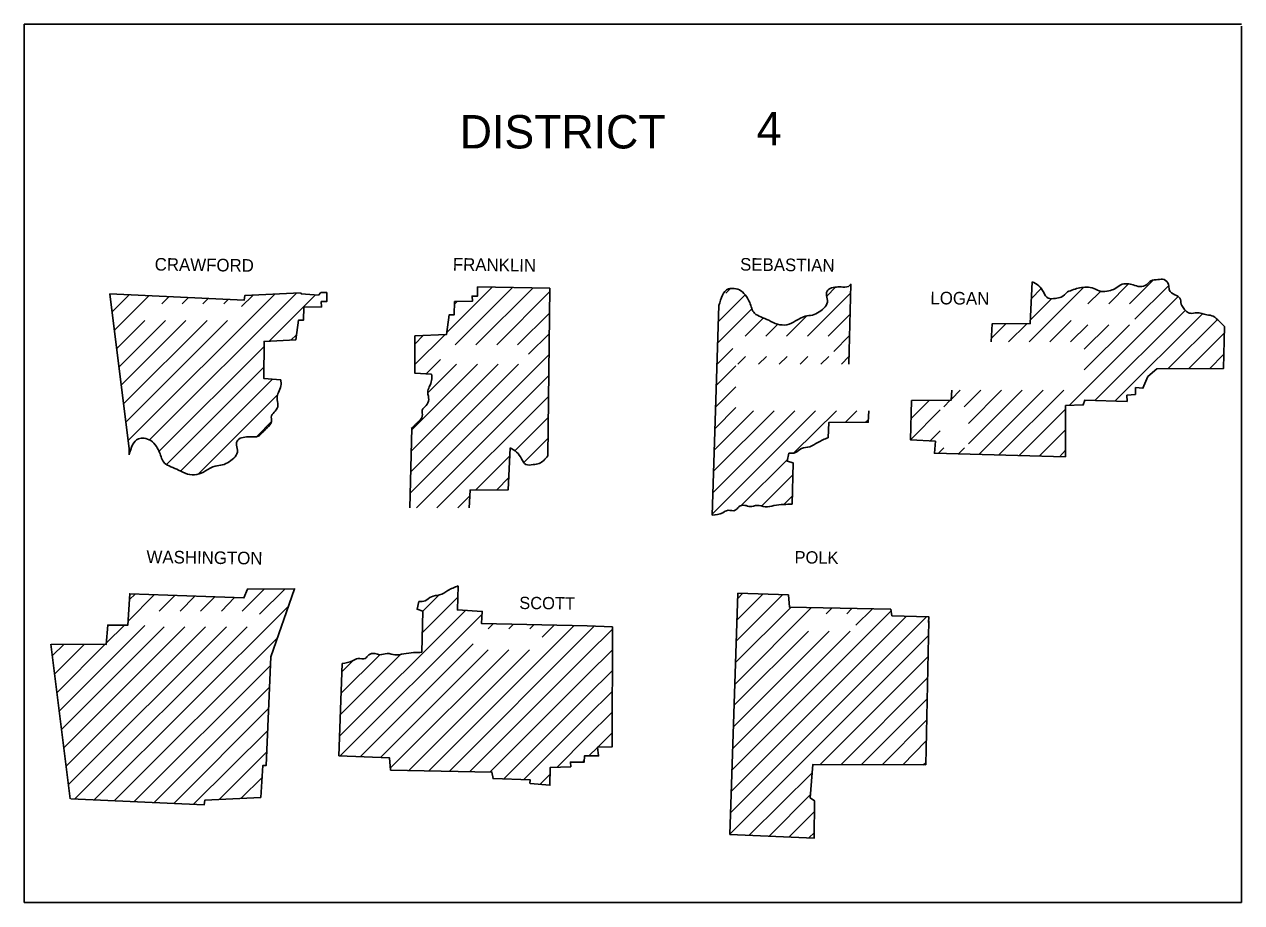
# Model space of a CAD drawing. Extents: x 76 to 6945, y -3933 to 2152.
# Drawn here: x 6125.3 to 6541, y -2439.5 to -2139.5 of the extents above; entities that cross this region are included whole.
import ezdxf

# ---------------------------------------------------------------- set-up
doc = ezdxf.new("R2010")
doc.units = 0
doc.layers.add('R_Draft', color=7, linetype='Continuous')

msp = doc.modelspace()

# ---------------------------------------------------------------- linework, layer by layer
at = {"layer": 'R_Draft'}
msp.add_line((6541.01, -2140.12), (6541.01, -2439.52), dxfattribs=at)
for points in [[(6125.31, -2439.52), (6125.31, -2139.52), (6541.01, -2139.52)], [(6455.51, -2248.02), (6455.81, -2241.82), (6468.81, -2241.72), (6469.51, -2227.42)], [(6502.71, -2235.02), (6510.71, -2227.02)], [(6154.51, -2231.62), (6200.41, -2233.72), (6200.61, -2232.12), (6219.61, -2231.22)], [(6161.11, -2286.52), (6161.11, -2284.52), (6154.51, -2231.62)], [(6155.31, -2237.72), (6161.11, -2231.92)], [(6156.11, -2244.02), (6167.81, -2232.22)], [(6160.81, -2281.62), (6210.81, -2231.72)], [(6168.11, -2281.42), (6218.31, -2231.32)], [(6199.51, -2235.92), (6203.31, -2232.12)], [(6228.61, -2231.12), (6228.61, -2234.22), (6226.71, -2234.22), (6226.81, -2236.02), (6220.71, -2236.12), (6220.61, -2240.62), (6218.91, -2240.62), (6218.01, -2247.32), (6207.21, -2247.82), (6207.11, -2260.52), (6212.91, -2260.92)], [(6208.91, -2247.72), (6224.71, -2231.92)], [(6219.81, -2231.22), (6219.81, -2231.52), (6225.71, -2232.02), (6226.61, -2231.12), (6228.61, -2231.12)], [(6264.41, -2259.02), (6258.61, -2258.62), (6258.71, -2245.92), (6269.51, -2245.42), (6270.41, -2238.72), (6272.11, -2238.72), (6272.21, -2234.22), (6278.31, -2234.12), (6278.21, -2232.32), (6280.11, -2232.32), (6280.11, -2229.22)], [(6269.61, -2244.82), (6285.01, -2229.42)], [(6272.41, -2249.02), (6292.01, -2229.42)], [(6279.51, -2249.02), (6298.91, -2229.62)], [(6280.11, -2229.22), (6304.81, -2229.62)], [(6286.61, -2249.02), (6304.71, -2230.82)], [(6304.81, -2229.62), (6304.11, -2286.92)], [(6362.21, -2241.12), (6371.41, -2232.02)], [(6364.91, -2231.32), (6366.61, -2229.62)], [(6392.71, -2246.02), (6407.51, -2231.22)], [(6399.31, -2232.32), (6402.31, -2229.32)], [(6407.61, -2228.22), (6406.91, -2255.62)], [(6468.41, -2248.02), (6487.01, -2229.42)], [(6469.21, -2233.12), (6472.41, -2229.92)], [(6488.51, -2235.02), (6492.81, -2230.72)], [(6495.61, -2235.02), (6502.31, -2228.32)], [(6504.51, -2240.22), (6516.01, -2228.82)], [(6172.21, -2235.02), (6174.61, -2232.62)], [(6179.21, -2235.02), (6181.31, -2232.92)], [(6186.21, -2235.02), (6188.11, -2233.12)], [(6193.41, -2235.02), (6194.91, -2233.52)], [(6272.11, -2235.22), (6273.11, -2234.22)], [(6360.21, -2307.22), (6362.51, -2235.52)], [(6468.81, -2240.62), (6476.01, -2233.42)], [(6482.21, -2269.62), (6519.21, -2232.62)], [(6293.71, -2249.02), (6304.71, -2238.02)], [(6362.11, -2248.32), (6373.81, -2236.62)], [(6371.51, -2246.02), (6377.61, -2239.92)], [(6385.61, -2246.02), (6392.61, -2239.02)], [(6399.81, -2246.02), (6407.31, -2238.52)], [(6490.91, -2268.02), (6521.71, -2237.22)], [(6497.71, -2268.22), (6527.61, -2238.42)], [(6515.81, -2257.22), (6532.71, -2240.32)], [(6156.91, -2250.22), (6166.51, -2240.72)], [(6157.71, -2256.52), (6173.51, -2240.72)], [(6158.41, -2262.82), (6180.51, -2240.72)], [(6159.21, -2269.12), (6187.71, -2240.72)], [(6160.01, -2275.42), (6194.71, -2240.72)], [(6378.51, -2246.02), (6382.51, -2242.02)], [(6455.61, -2246.72), (6460.51, -2241.82)], [(6461.41, -2248.02), (6467.61, -2241.82)], [(6475.51, -2248.02), (6482.81, -2240.72)], [(6535.21, -2242.72), (6534.81, -2257.12), (6512.01, -2257.22), (6509.01, -2259.82), (6507.31, -2263.82), (6504.81, -2263.62), (6504.71, -2265.92), (6501.81, -2266.22), (6501.91, -2268.32), (6487.41, -2267.92), (6486.91, -2269.52), (6480.91, -2269.72), (6480.81, -2287.22)], [(6482.61, -2248.02), (6488.51, -2242.12)], [(6487.21, -2257.52), (6502.71, -2242.12)], [(6487.21, -2250.52), (6495.61, -2242.12)], [(6216.31, -2247.42), (6218.21, -2245.52)], [(6258.61, -2255.72), (6268.91, -2245.52)], [(6258.61, -2248.72), (6261.51, -2245.82)], [(6297.51, -2252.22), (6304.61, -2245.12)], [(6401.71, -2251.22), (6407.11, -2245.82)], [(6522.91, -2257.22), (6535.11, -2244.92)], [(6171.41, -2285.32), (6207.21, -2249.52)], [(6257.01, -2299.82), (6304.51, -2252.32)], [(6361.91, -2255.62), (6367.31, -2250.22)], [(6368.91, -2255.62), (6371.61, -2252.92)], [(6376.01, -2255.62), (6378.71, -2252.92)], [(6383.11, -2255.62), (6385.81, -2252.92)], [(6390.21, -2255.62), (6392.91, -2252.92)], [(6397.31, -2255.62), (6400.01, -2252.92)], [(6404.31, -2255.62), (6406.91, -2253.02)], [(6530.01, -2257.22), (6534.91, -2252.22)], [(6173.91, -2289.82), (6207.21, -2256.52)], [(6257.21, -2292.52), (6294.11, -2255.62)], [(6257.41, -2285.32), (6287.11, -2255.62)], [(6257.61, -2278.02), (6280.01, -2255.62)], [(6262.61, -2258.82), (6267.41, -2254.02)], [(6263.21, -2265.32), (6272.91, -2255.62)], [(6361.61, -2262.92), (6368.31, -2256.22)], [(6178.71, -2292.02), (6210.11, -2260.72)], [(6259.21, -2304.72), (6304.41, -2259.52)], [(6361.41, -2270.22), (6368.31, -2263.32)], [(6480.81, -2287.22), (6436.11, -2286.02), (6436.41, -2281.92), (6427.91, -2281.42), (6428.31, -2268.02), (6441.81, -2267.92), (6442.01, -2264.52)], [(6441.91, -2267.52), (6444.91, -2264.52)], [(6446.31, -2270.12), (6451.91, -2264.52)], [(6447.71, -2282.82), (6466.11, -2264.52)], [(6447.71, -2275.82), (6459.01, -2264.52)], [(6451.31, -2286.42), (6473.21, -2264.52)], [(6458.11, -2286.62), (6480.31, -2264.52)], [(6184.71, -2293.12), (6211.81, -2266.12)], [(6266.21, -2304.72), (6304.31, -2266.62)], [(6428.21, -2274.12), (6434.41, -2267.92)], [(6439.31, -2270.12), (6441.51, -2267.92)], [(6293.01, -2285.02), (6304.21, -2273.82)], [(6360.31, -2306.72), (6395.51, -2271.52)], [(6360.51, -2299.42), (6388.41, -2271.52)], [(6360.71, -2292.12), (6381.41, -2271.52)], [(6360.91, -2284.92), (6374.31, -2271.52)], [(6361.21, -2277.52), (6368.31, -2270.42)], [(6388.11, -2285.92), (6402.61, -2271.52)], [(6413.71, -2271.52), (6413.51, -2275.42), (6400.01, -2275.52), (6399.81, -2280.72)], [(6405.71, -2275.42), (6409.61, -2271.52)], [(6427.91, -2281.42), (6438.11, -2271.22)], [(6465.11, -2286.72), (6481.01, -2270.82)], [(6204.81, -2280.22), (6209.71, -2275.22)], [(6256.91, -2304.72), (6257.61, -2277.42)], [(6412.71, -2275.42), (6413.51, -2274.72)], [(6471.91, -2287.02), (6481.01, -2277.92)], [(6296.01, -2289.02), (6304.21, -2280.92)], [(6434.71, -2281.72), (6438.11, -2278.32)], [(6291.21, -2284.22), (6290.51, -2298.52), (6277.51, -2298.62), (6277.21, -2304.72)], [(6386.41, -2286.02), (6385.81, -2288.72), (6387.81, -2289.32), (6387.51, -2303.42)], [(6437.51, -2286.02), (6439.31, -2284.22)], [(6444.31, -2286.22), (6446.41, -2284.22)], [(6478.81, -2287.22), (6480.91, -2285.02)], [(6279.41, -2298.62), (6291.21, -2286.82)], [(6370.11, -2303.92), (6385.91, -2288.12)], [(6286.61, -2298.52), (6290.71, -2294.32)], [(6377.11, -2304.02), (6387.81, -2293.32)], [(6273.31, -2304.72), (6277.41, -2300.62)], [(6384.81, -2303.42), (6387.61, -2300.62)], [(6273.41, -2331.32), (6273.21, -2339.52), (6281.71, -2340.02), (6281.41, -2344.12), (6317.51, -2345.02)], [(6134.61, -2351.22), (6153.31, -2351.32), (6153.81, -2344.72), (6160.71, -2344.72), (6161.31, -2334.02), (6200.31, -2335.42), (6201.51, -2332.42), (6217.61, -2332.32), (6209.51, -2355.52), (6207.91, -2392.62), (6206.71, -2392.72), (6206.11, -2403.62)], [(6160.81, -2343.42), (6169.81, -2334.32)], [(6161.21, -2336.02), (6163.11, -2334.12)], [(6171.41, -2339.92), (6176.71, -2334.62)], [(6178.51, -2339.92), (6183.51, -2334.82)], [(6185.51, -2339.92), (6190.41, -2335.02)], [(6192.61, -2339.92), (6197.11, -2335.32)], [(6199.71, -2339.92), (6207.21, -2332.42)], [(6205.61, -2341.02), (6214.31, -2332.42)], [(6261.31, -2340.12), (6266.91, -2334.52)], [(6261.31, -2347.22), (6273.31, -2335.22)], [(6366.21, -2416.22), (6369.01, -2333.82)], [(6368.51, -2350.12), (6384.21, -2334.42)], [(6368.71, -2342.92), (6377.41, -2334.22)], [(6368.91, -2333.82), (6386.21, -2334.42), (6386.61, -2338.62), (6421.21, -2339.32), (6421.61, -2341.52), (6434.21, -2341.92), (6434.11, -2343.82)], [(6368.91, -2335.62), (6370.61, -2333.92)], [(6149.31, -2404.32), (6215.51, -2338.22)], [(6232.91, -2382.62), (6275.91, -2339.72)], [(6261.11, -2354.02), (6261.41, -2339.92), (6259.41, -2339.32), (6260.01, -2336.62)], [(6367.01, -2394.12), (6421.31, -2339.82)], [(6368.01, -2364.92), (6394.01, -2338.82)], [(6368.21, -2357.52), (6387.01, -2338.72)], [(6399.11, -2340.82), (6400.91, -2339.02)], [(6406.21, -2340.82), (6407.81, -2339.12)], [(6409.31, -2344.72), (6414.81, -2339.32)], [(6233.21, -2389.42), (6281.51, -2341.12)], [(6283.71, -2346.02), (6285.51, -2344.22)], [(6290.81, -2346.02), (6292.31, -2344.42)], [(6434.21, -2343.22), (6433.11, -2392.42), (6394.61, -2392.32), (6393.71, -2403.72), (6395.11, -2404.72), (6395.01, -2417.52), (6366.21, -2416.22)], [(6366.51, -2408.82), (6433.41, -2341.92)], [(6366.81, -2401.42), (6426.51, -2341.72)], [(6137.21, -2374.12), (6166.51, -2344.82)], [(6138.01, -2380.42), (6173.11, -2345.32)], [(6138.81, -2386.62), (6180.11, -2345.32)], [(6139.61, -2392.92), (6187.21, -2345.32)], [(6140.41, -2399.22), (6194.31, -2345.32)], [(6142.61, -2404.02), (6201.41, -2345.32)], [(6153.41, -2350.82), (6159.51, -2344.72)], [(6263.61, -2394.42), (6313.01, -2345.02)], [(6270.51, -2394.62), (6317.51, -2347.52)], [(6297.91, -2346.02), (6299.31, -2344.62)], [(6302.11, -2348.82), (6306.11, -2344.82)], [(6317.51, -2345.02), (6326.11, -2345.32)], [(6317.51, -2347.52), (6319.91, -2345.12)], [(6326.11, -2345.32), (6326.01, -2386.32), (6321.01, -2386.42), (6321.41, -2389.42), (6317.51, -2389.32)], [(6317.51, -2354.62), (6326.11, -2346.12)], [(6366.31, -2416.02), (6434.11, -2348.22)], [(6367.21, -2386.82), (6407.31, -2346.82)], [(6367.51, -2379.52), (6400.21, -2346.82)], [(6367.71, -2372.12), (6393.11, -2346.82)], [(6140.91, -2404.02), (6134.31, -2351.22)], [(6134.81, -2355.22), (6138.91, -2351.22)], [(6135.61, -2361.52), (6145.91, -2351.22)], [(6136.41, -2367.82), (6152.91, -2351.22)], [(6156.11, -2404.62), (6211.71, -2349.02)], [(6240.11, -2389.62), (6278.61, -2351.12)], [(6233.21, -2375.32), (6253.91, -2354.62)], [(6233.51, -2367.92), (6246.71, -2354.82)], [(6246.91, -2389.92), (6283.71, -2353.12)], [(6250.41, -2393.42), (6290.81, -2353.12)], [(6256.71, -2394.22), (6297.81, -2353.12)], [(6277.41, -2394.72), (6317.51, -2354.62)], [(6317.51, -2361.72), (6326.11, -2353.12)], [(6397.11, -2392.32), (6433.91, -2355.42)], [(6162.81, -2405.02), (6209.41, -2358.52)], [(6232.71, -2389.42), (6233.81, -2357.82)], [(6233.81, -2360.62), (6237.41, -2357.02)], [(6317.51, -2368.82), (6326.11, -2360.22)], [(6284.31, -2394.92), (6317.51, -2361.72)], [(6404.21, -2392.32), (6433.71, -2362.72)], [(6169.61, -2405.32), (6209.01, -2365.92)], [(6289.21, -2397.12), (6317.51, -2368.82)], [(6317.51, -2375.82), (6326.01, -2367.42)], [(6176.41, -2405.62), (6208.71, -2373.22)], [(6411.21, -2392.32), (6433.61, -2369.92)], [(6295.91, -2397.42), (6317.51, -2375.82)], [(6317.51, -2382.92), (6326.01, -2374.42)], [(6418.21, -2392.42), (6433.41, -2377.22)], [(6183.11, -2405.92), (6208.41, -2380.72)], [(6321.11, -2386.42), (6326.01, -2381.52)], [(6307.31, -2393.22), (6317.51, -2382.92)], [(6425.31, -2392.42), (6433.21, -2384.42)], [(6191.81, -2404.32), (6208.01, -2388.12)], [(6297.91, -2398.82), (6298.01, -2397.52), (6285.41, -2397.12), (6285.01, -2394.92), (6250.41, -2394.22), (6250.01, -2390.02), (6232.71, -2389.42)], [(6317.51, -2389.32), (6316.61, -2389.32), (6316.51, -2391.52), (6311.81, -2391.52), (6311.91, -2393.12), (6304.91, -2393.32), (6304.81, -2399.42), (6298.01, -2398.82)], [(6318.11, -2389.32), (6321.01, -2386.52)], [(6316.01, -2391.52), (6316.51, -2391.02)], [(6432.41, -2392.42), (6433.11, -2391.72)], [(6199.31, -2403.82), (6206.51, -2396.72)], [(6301.41, -2399.02), (6304.91, -2395.62)], [(6372.81, -2416.52), (6394.41, -2395.02)], [(6379.61, -2416.82), (6393.81, -2402.62)], [(6206.11, -2403.62), (6186.91, -2404.52), (6186.71, -2406.12), (6141.21, -2404.02)], [(6386.41, -2417.12), (6395.11, -2408.42)], [(6393.21, -2417.42), (6395.11, -2415.52)], [(6541.01, -2439.52), (6125.31, -2439.52)]]:
    msp.add_lwpolyline(points, dxfattribs=at)
for points in [[(6362.51, -2235.52), (6365.81, -2229.92), (6367.71, -2229.72), (6370.01, -2230.52), (6371.91, -2232.52), (6373.01, -2234.52), (6374.71, -2238.22), (6376.81, -2239.42), (6379.51, -2240.62), (6382.51, -2241.92), (6385.71, -2242.12), (6388.71, -2240.82), (6392.01, -2239.22), (6394.41, -2238.82), (6396.71, -2237.72), (6398.81, -2236.02), (6399.61, -2233.82), (6399.21, -2231.52), (6400.01, -2230.02), (6402.11, -2229.32), (6404.21, -2229.22), (6406.71, -2229.02), (6407.71, -2228.12)], [(6469.51, -2227.42), (6471.71, -2228.82), (6473.41, -2231.12), (6474.91, -2233.02), (6477.41, -2233.12), (6479.41, -2232.72), (6481.51, -2230.92)], [(6481.51, -2230.92), (6485.71, -2229.52), (6488.11, -2229.32), (6490.51, -2229.72), (6493.01, -2230.72), (6495.71, -2230.52), (6497.71, -2229.82), (6499.71, -2228.52), (6501.91, -2228.12), (6504.01, -2228.52), (6506.21, -2229.12), (6508.61, -2228.42), (6510.01, -2227.12), (6512.41, -2226.72), (6514.51, -2226.72), (6516.01, -2228.42), (6516.31, -2230.22), (6518.21, -2231.92), (6519.91, -2233.02), (6520.41, -2235.12), (6521.31, -2236.62), (6522.21, -2237.62), (6523.51, -2238.22), (6525.71, -2238.02), (6529.11, -2238.72), (6531.31, -2239.22), (6533.31, -2240.92), (6535.21, -2242.72)], [(6212.91, -2260.92), (6212.91, -2263.02), (6212.11, -2265.22), (6211.61, -2267.12), (6211.91, -2269.62), (6211.01, -2271.62), (6209.71, -2273.22), (6209.71, -2275.22), (6208.21, -2277.32), (6206.61, -2278.92), (6205.21, -2280.22), (6202.71, -2280.42), (6200.61, -2280.52), (6198.51, -2281.22), (6197.71, -2282.72), (6198.11, -2285.02), (6197.31, -2287.22), (6195.21, -2288.92), (6192.91, -2290.02), (6190.51, -2290.42), (6187.21, -2292.02), (6184.21, -2293.32), (6181.01, -2293.12), (6178.01, -2291.82), (6175.31, -2290.62), (6173.21, -2289.42), (6171.51, -2285.72), (6170.41, -2283.72), (6168.51, -2281.72), (6166.21, -2280.92), (6164.31, -2281.12), (6161.11, -2286.52)], [(6257.41, -2277.62), (6258.11, -2277.02), (6259.71, -2275.42), (6261.21, -2273.32), (6261.21, -2271.32), (6262.51, -2269.72), (6263.41, -2267.72), (6263.11, -2265.22), (6263.61, -2263.32), (6264.41, -2261.12), (6264.41, -2259.02)], [(6399.81, -2280.72), (6396.31, -2282.32), (6393.51, -2283.82), (6390.71, -2284.42), (6388.61, -2285.82), (6386.41, -2286.02)], [(6304.11, -2286.92), (6301.11, -2289.52), (6299.11, -2289.92), (6296.61, -2289.82), (6295.11, -2287.92), (6293.41, -2285.62), (6291.21, -2284.22)], [(6387.51, -2303.42), (6384.61, -2303.52), (6381.31, -2303.92), (6378.31, -2304.32), (6375.61, -2303.82), (6373.11, -2304.22), (6371.41, -2303.82), (6369.31, -2304.32), (6368.11, -2305.52), (6365.61, -2305.52), (6363.81, -2306.32), (6360.21, -2307.22)], [(6260.01, -2336.62), (6262.21, -2336.42), (6264.31, -2335.02), (6267.11, -2334.42), (6269.91, -2332.92), (6273.41, -2331.32)], [(6233.81, -2357.82), (6237.41, -2356.92), (6239.21, -2356.12), (6241.71, -2356.12), (6242.91, -2354.92), (6245.01, -2354.42), (6246.71, -2354.82), (6249.21, -2354.42), (6251.91, -2354.92), (6254.91, -2354.52), (6258.21, -2354.12), (6261.11, -2354.02)]]:
    msp.add_spline(points, degree=3, dxfattribs=at)

# ---------------------------------------------------------------- texts
for s, p in [('4', (6375.41, -2180.82)), ('DISTRICT', (6274.01, -2181.92))]:
    msp.add_text(s, height=11.4, dxfattribs=at).set_placement(p)
for s, height, rotation, p in [('CRAWFORD', 4.3, 359.2771, (6169.81, -2223.62)), ('FRANKLIN', 4.301, 359.1815, (6271.61, -2223.62)), ('SEBASTIAN', 4.3, 359.2816, (6369.71, -2223.62)), ('LOGAN', 4.301, 359.3969, (6434.71, -2235.12)), ('WASHINGTON', 4.3, 359.232, (6167.01, -2323.52)), ('POLK', 4.199, 359.2152, (6388.31, -2323.62)), ('SCOTT', 4.201, 359.4063, (6294.31, -2339.22))]:
    msp.add_text(s, height=height, rotation=rotation, dxfattribs=at).set_placement(p)

doc.saveas('drawing.dxf')
